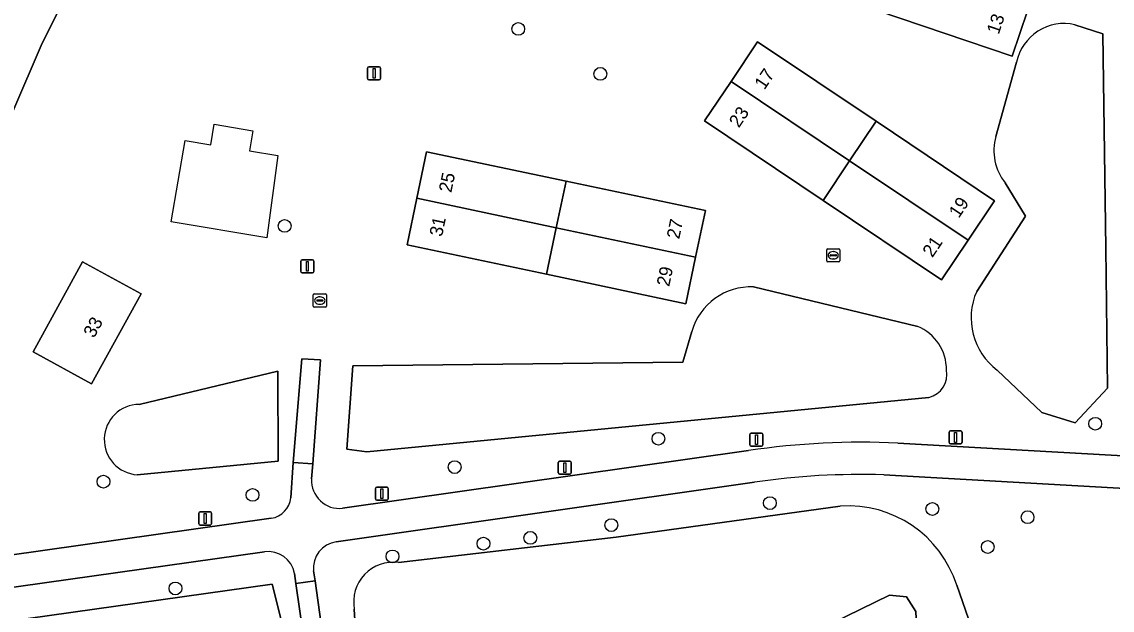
# Model space of a CAD drawing. Extents: x 159451 to 160664, y 388402 to 389723.
# Drawn here: x 159502.7 to 159586.1, y 389293.3 to 389338.3 of the extents above; entities that cross this region are included whole.
import ezdxf

# ---------------------------------------------------------------- set-up
doc = ezdxf.new("R2010")
doc.units = 0
for name, color, linetype in [('IMGEO_Boom', 7, 'Continuous'), ('IMGEO_Bouwland', 7, 'Continuous'), ('IMGEO_Groenvoorziening', 7, 'Continuous'), ('IMGEO_Lichtmast', 7, 'Continuous'), ('IMGEO_Loofbos', 7, 'Continuous'), ('IMGEO_Meer_plas_ven_vijver', 7, 'Continuous'), ('IMGEO_Pand', 7, 'Continuous'), ('IMGEO_Pand_nummerreeks', 7, 'Continuous'), ('IMGEO_Pand_vergunning_verleend', 7, 'Continuous'), ('IMGEO_Rijbaan_lokaal_gesloten', 7, 'Continuous'), ('IMGEO_Rioolput', 7, 'Continuous')]:
    doc.layers.add(name, color=color, linetype=linetype)

msp = doc.modelspace()

# ---------------------------------------------------------------- linework, layer by layer
at = {"layer": 'IMGEO_Boom'}
for centre in [(159540.673, 389337.725), (159546.954, 389334.287), (159522.8, 389322.657), (159584.813, 389307.527), (159551.396, 389306.381), (159535.811, 389304.209), (159508.939, 389303.101), (159520.344, 389302.083), (159559.924, 389301.457), (159572.353, 389301.007), (159579.641, 389300.381), (159547.792, 389299.774), (159538.012, 389298.356), (159541.597, 389298.799), (159531.052, 389297.376), (159576.591, 389298.104), (159514.448, 389294.93)]:
    msp.add_circle(centre, 0.489, dxfattribs=at)
at = {"layer": 'IMGEO_Bouwland'}
for points in [[(159521.25, 389297.74), (159493.172, 389293.777), (159486.712, 389292.863), (159536.847, 389188.304)], [(159525.256, 389283.811), (159524.796, 389287.372), (159523.669, 389295.299), (159523.555, 389296.061)]]:
    msp.add_lwpolyline(points, dxfattribs=at)
msp.add_lwpolyline([(159511.894, 389259.653), (159514.744, 389257.84), (159515.886, 389256.055), (159517.22, 389247.851), (159518.659, 389246.126), (159521.069, 389241.65), (159515.724, 389239.283), (159511.127, 389249.352), (159494.743, 389289.39), (159494.831, 389290.177), (159496.278, 389291.663), (159521.85, 389295.267), (159523.74, 389287.733), (159509.011, 389285.515), (159504.61, 389284.226)], close=True, dxfattribs=at)
msp.add_arc((159521.518, 389295.687), 2.071, 10.41627, 97.44331, dxfattribs=at)
at = {"layer": 'IMGEO_Groenvoorziening'}
for points in [[(159544.814, 389411.565), (159514.866, 389357.937), (159504.183, 389336.444), (159491.991, 389308.123), (159485.81, 389295.214), (159492.759, 389296.199), (159521.777, 389300.297)], [(159583.265, 389338.049), (159585.405, 389337.346)], [(159585.405, 389337.346), (159585.616, 389320.948), (159585.756, 389310.259), (159583.269, 389307.588), (159580.724, 389308.383), (159577.303, 389311.626)], [(159577.217, 389329.496), (159578.8, 389335.179)], [(159575.746, 389317.652), (159579.475, 389323.392), (159577.93, 389325.941)], [(159558.673, 389317.997), (159571.236, 389314.976)], [(159572.076, 389309.541), (159529.1, 389305.373), (159527.548, 389305.578), (159528.023, 389311.95), (159553.255, 389312.241), (159553.948, 389314.586)], [(159523.268, 389301.867), (159523.448, 389304.552), (159524.108, 389312.501), (159525.556, 389312.414), (159524.968, 389304.47), (159524.866, 389303.302)], [(159511.676, 389309.006), (159522.275, 389311.536), (159522.313, 389304.654)], [(159527.236, 389301.062), (159558.3, 389305.469)], [(159569.711, 389306.038), (159612.776, 389303.614), (159612.166, 389303.421), (159612.757, 389303.197), (159612.044, 389302.952), (159612.655, 389302.565), (159611.86, 389302.198), (159612.513, 389301.851), (159611.84, 389301.566), (159612.27, 389301.143), (159568.631, 389303.617)], [(159522.313, 389304.654), (159511.527, 389303.624)], [(159558.75, 389303.048), (159526.743, 389298.498)], [(159531.514, 389296.911), (159548.156, 389298.841), (159565.312, 389301.228)], [(159525.003, 389296.267), (159525.136, 389295.518), (159526.226, 389287.573), (159526.723, 389284.029)], [(159574.217, 389295.171), (159576.492, 389288.625), (159580.643, 389278.999), (159585.177, 389266.997), (159588.35, 389258.709)], [(159571.755, 389279.564), (159571.085, 389293.162), (159570.386, 389294.298), (159569.066, 389294.418), (159562.535, 389291.222)], [(159528.272, 389290.814), (159528.13, 389293.352)]]:
    msp.add_lwpolyline(points, dxfattribs=at)
for points in [[(159578.47, 389335.651), (159568.144, 389339.143), (159557.83, 389342.632), (159558.992, 389346.082), (159560.158, 389349.546), (159570.482, 389346.054), (159580.805, 389342.563), (159579.637, 389339.107)], [(159568.05, 389330.657), (159577.112, 389324.582), (159575.085, 389321.557), (159573.057, 389318.531), (159563.994, 389324.607), (159554.929, 389330.685), (159556.956, 389333.705), (159558.987, 389336.732)], [(159554.238, 389320.27), (159553.487, 389316.706), (159542.824, 389318.958), (159532.162, 389321.21), (159532.912, 389324.767), (159533.664, 389328.332), (159544.327, 389326.082), (159554.99, 389323.833)], [(159511.812, 389317.468), (159508.032, 389310.567), (159503.562, 389313.015), (159507.34, 389319.922)]]:
    msp.add_lwpolyline(points, close=True, dxfattribs=at)
for centre, radius, start, end in [((159582.45, 389334.409), 3.73, 77.37547, 168.0885), ((159580.971, 389328.4), 3.911, 163.72297, 218.95888), ((159558.496, 389313.264), 4.736, 87.85852, 163.79288), ((159580.344, 389315.626), 5.024, 156.21696, 232.75756), ((159569.834, 389311.66), 3.6, 359.71074, 67.08044), ((159571.661, 389311.298), 1.806, 283.27906, 10.96701), ((159511.697, 389306.312), 2.694, 90.44666, 266.3817), ((159566.832, 389249.071), 57.04, 87.10675, 98.60253), ((159566.807, 389249.211), 54.436, 88.07992, 98.51159), ((159526.998, 389303.184), 2.135, 176.82421, 276.40637), ((159521.497, 389302.056), 1.781, 279.04609, 353.91069), ((159565.905, 389292.525), 8.723, 17.65678, 93.89774), ((159527.037, 389296.475), 2.044, 98.26043, 185.83686), ((159531.116, 389293.901), 3.036, 82.46825, 190.41944)]:
    msp.add_arc(centre, radius, start, end, dxfattribs=at)
at = {"layer": 'IMGEO_Lichtmast'}
for p, q in [((159529.146, 389333.929), (159529.146, 389334.729)), ((159529.146, 389334.729), (159529.146, 389333.929)), ((159529.246, 389334.829), (159530.036, 389334.829)), ((159530.036, 389334.829), (159529.246, 389334.829)), ((159530.136, 389334.729), (159530.136, 389333.929)), ((159530.136, 389333.929), (159530.136, 389334.729)), ((159530.036, 389333.829), (159529.246, 389333.829)), ((159529.246, 389333.829), (159530.036, 389333.829)), ((159524.042, 389319.163), (159524.042, 389319.963)), ((159524.042, 389319.963), (159524.042, 389319.163)), ((159524.142, 389320.063), (159524.932, 389320.063)), ((159524.932, 389320.063), (159524.142, 389320.063)), ((159525.032, 389319.963), (159525.032, 389319.163)), ((159525.032, 389319.163), (159525.032, 389319.963)), ((159524.932, 389319.063), (159524.142, 389319.063)), ((159524.142, 389319.063), (159524.932, 389319.063)), ((159573.733, 389306.98), (159574.523, 389306.98)), ((159574.523, 389306.98), (159573.733, 389306.98)), ((159558.399, 389305.91), (159558.399, 389306.71)), ((159558.399, 389306.71), (159558.399, 389305.91)), ((159558.499, 389306.81), (159559.289, 389306.81)), ((159559.289, 389306.81), (159558.499, 389306.81)), ((159559.389, 389306.71), (159559.389, 389305.91)), ((159559.389, 389305.91), (159559.389, 389306.71)), ((159573.633, 389306.08), (159573.633, 389306.88)), ((159573.633, 389306.88), (159573.633, 389306.08)), ((159574.623, 389306.88), (159574.623, 389306.08)), ((159574.623, 389306.08), (159574.623, 389306.88)), ((159559.289, 389305.81), (159558.499, 389305.81)), ((159558.499, 389305.81), (159559.289, 389305.81)), ((159574.523, 389305.98), (159573.733, 389305.98)), ((159573.733, 389305.98), (159574.523, 389305.98)), ((159543.739, 389303.773), (159543.739, 389304.573)), ((159543.739, 389304.573), (159543.739, 389303.773)), ((159543.839, 389304.673), (159544.629, 389304.673)), ((159544.629, 389304.673), (159543.839, 389304.673)), ((159544.729, 389304.573), (159544.729, 389303.773)), ((159544.729, 389303.773), (159544.729, 389304.573)), ((159544.629, 389303.673), (159543.839, 389303.673)), ((159543.839, 389303.673), (159544.629, 389303.673)), ((159529.742, 389301.778), (159529.742, 389302.578)), ((159529.742, 389302.578), (159529.742, 389301.778)), ((159529.842, 389302.678), (159530.632, 389302.678)), ((159530.632, 389302.678), (159529.842, 389302.678)), ((159530.732, 389302.578), (159530.732, 389301.778)), ((159530.732, 389301.778), (159530.732, 389302.578)), ((159530.632, 389301.678), (159529.842, 389301.678)), ((159529.842, 389301.678), (159530.632, 389301.678)), ((159516.227, 389299.881), (159516.227, 389300.681)), ((159516.227, 389300.681), (159516.227, 389299.881)), ((159516.327, 389300.781), (159517.117, 389300.781)), ((159517.117, 389300.781), (159516.327, 389300.781)), ((159517.217, 389300.681), (159517.217, 389299.881)), ((159517.217, 389299.881), (159517.217, 389300.681)), ((159517.117, 389299.781), (159516.327, 389299.781)), ((159516.327, 389299.781), (159517.117, 389299.781))]:
    msp.add_line(p, q, dxfattribs=at)
for points in [[(159529.566, 389334.704), (159529.716, 389334.704), (159529.716, 389333.954), (159529.566, 389333.954), (159529.566, 389334.704)], [(159524.462, 389319.938), (159524.612, 389319.938), (159524.612, 389319.188), (159524.462, 389319.188), (159524.462, 389319.938)], [(159558.819, 389306.685), (159558.969, 389306.685), (159558.969, 389305.935), (159558.819, 389305.935), (159558.819, 389306.685)], [(159574.053, 389306.855), (159574.203, 389306.855), (159574.203, 389306.105), (159574.053, 389306.105), (159574.053, 389306.855)], [(159544.159, 389304.548), (159544.309, 389304.548), (159544.309, 389303.798), (159544.159, 389303.798), (159544.159, 389304.548)], [(159530.162, 389302.553), (159530.312, 389302.553), (159530.312, 389301.803), (159530.162, 389301.803), (159530.162, 389302.553)], [(159516.647, 389300.656), (159516.797, 389300.656), (159516.797, 389299.906), (159516.647, 389299.906), (159516.647, 389300.656)]]:
    msp.add_lwpolyline(points, dxfattribs=at)
for centre, start, end in [((159529.246, 389334.729), 90, 180), ((159529.246, 389334.729), 90, 180), ((159530.036, 389334.729), 0, 90), ((159530.036, 389334.729), 360, 90), ((159529.246, 389333.929), 180, 270), ((159529.246, 389333.929), 180, 270), ((159530.036, 389333.929), 270, 0), ((159530.036, 389333.929), 270, 0), ((159524.142, 389319.963), 90, 180), ((159524.142, 389319.963), 90, 180), ((159524.932, 389319.963), 0, 90), ((159524.932, 389319.963), 360, 90), ((159524.142, 389319.163), 180, 270), ((159524.142, 389319.163), 180, 270), ((159524.932, 389319.163), 270, 0), ((159524.932, 389319.163), 270, 0), ((159573.733, 389306.88), 90, 180), ((159573.733, 389306.88), 90, 180), ((159574.523, 389306.88), 0, 90), ((159574.523, 389306.88), 360, 90), ((159558.499, 389306.71), 90, 180), ((159558.499, 389306.71), 90, 180), ((159559.289, 389306.71), 0, 90), ((159559.289, 389306.71), 360, 90), ((159558.499, 389305.91), 180, 270), ((159558.499, 389305.91), 180, 270), ((159559.289, 389305.91), 270, 0), ((159559.289, 389305.91), 270, 0), ((159573.733, 389306.08), 180, 270), ((159573.733, 389306.08), 180, 270), ((159574.523, 389306.08), 270, 0), ((159574.523, 389306.08), 270, 0), ((159543.839, 389304.573), 90, 180), ((159543.839, 389304.573), 90, 180), ((159544.629, 389304.573), 0, 90), ((159544.629, 389304.573), 360, 90), ((159543.839, 389303.773), 180, 270), ((159543.839, 389303.773), 180, 270), ((159544.629, 389303.773), 270, 0), ((159544.629, 389303.773), 270, 0), ((159529.842, 389302.578), 90, 180), ((159529.842, 389302.578), 90, 180), ((159530.632, 389302.578), 0, 90), ((159530.632, 389302.578), 360, 90), ((159529.842, 389301.778), 180, 270), ((159529.842, 389301.778), 180, 270), ((159530.632, 389301.778), 270, 0), ((159530.632, 389301.778), 270, 0), ((159516.327, 389300.681), 90, 180), ((159516.327, 389300.681), 90, 180), ((159517.117, 389300.681), 0, 90), ((159517.117, 389300.681), 360, 90), ((159516.327, 389299.881), 180, 270), ((159516.327, 389299.881), 180, 270), ((159517.117, 389299.881), 270, 0), ((159517.117, 389299.881), 270, 0)]:
    msp.add_arc(centre, 0.1, start, end, dxfattribs=at)
at = {"layer": 'IMGEO_Loofbos'}
msp.add_lwpolyline([(159475.093, 389317.376), (159476.799, 389293.936), (159485.81, 389295.214), (159491.991, 389308.123), (159504.183, 389336.444), (159514.866, 389357.937), (159544.814, 389411.565)], dxfattribs=at)
at = {"layer": 'IMGEO_Meer_plas_ven_vijver'}
for points in [[(159585.405, 389337.346), (159583.265, 389338.049)], [(159577.303, 389311.626), (159580.724, 389308.383), (159583.269, 389307.588), (159585.756, 389310.259), (159585.616, 389320.948), (159585.405, 389337.346)], [(159578.8, 389335.179), (159577.217, 389329.496)], [(159577.93, 389325.941), (159579.475, 389323.392), (159575.746, 389317.652)], [(159571.236, 389314.976), (159558.673, 389317.997)], [(159553.948, 389314.586), (159553.255, 389312.241), (159528.023, 389311.95), (159527.548, 389305.578), (159529.1, 389305.373), (159572.076, 389309.541)], [(159522.313, 389304.654), (159522.275, 389311.536), (159511.676, 389309.006)], [(159511.527, 389303.624), (159522.313, 389304.654)], [(159565.312, 389301.228), (159548.156, 389298.841), (159531.514, 389296.911)], [(159581.411, 389257.784), (159588.35, 389258.709), (159585.177, 389266.997), (159580.643, 389278.999), (159576.492, 389288.625), (159574.217, 389295.171)], [(159562.535, 389291.222), (159569.066, 389294.418), (159570.386, 389294.298), (159571.085, 389293.162), (159571.755, 389279.564)], [(159528.13, 389293.352), (159528.272, 389290.814)]]:
    msp.add_lwpolyline(points, dxfattribs=at)
msp.add_lwpolyline([(159521.069, 389241.65), (159518.659, 389246.126), (159517.22, 389247.851), (159515.886, 389256.055), (159514.744, 389257.84), (159511.894, 389259.653), (159504.61, 389284.226), (159509.011, 389285.515), (159523.74, 389287.733), (159521.85, 389295.267), (159496.278, 389291.663), (159494.831, 389290.177), (159494.743, 389289.39), (159511.127, 389249.352), (159515.724, 389239.283)], close=True, dxfattribs=at)
for centre, radius, start, end in [((159582.45, 389334.409), 3.73, 77.37547, 168.0885), ((159580.971, 389328.4), 3.911, 163.72297, 218.95888), ((159558.496, 389313.264), 4.736, 87.85852, 163.79288), ((159580.344, 389315.626), 5.024, 156.21696, 232.75756), ((159569.834, 389311.66), 3.6, 359.71074, 67.08044), ((159571.661, 389311.298), 1.806, 283.27906, 10.96701), ((159511.697, 389306.312), 2.694, 90.44666, 266.3817), ((159565.905, 389292.525), 8.723, 17.65678, 93.89774), ((159531.116, 389293.901), 3.036, 82.46825, 190.41944)]:
    msp.add_arc(centre, radius, start, end, dxfattribs=at)
at = {"layer": 'IMGEO_Pand'}
for points in [[(159569.312, 389342.595), (159568.144, 389339.143), (159578.47, 389335.651), (159579.637, 389339.107)], [(159558.987, 389336.732), (159556.956, 389333.705), (159566.021, 389327.63), (159568.05, 389330.657)], [(159556.956, 389333.705), (159554.929, 389330.685), (159563.994, 389324.607), (159566.021, 389327.63)], [(159568.05, 389330.657), (159566.021, 389327.63), (159575.085, 389321.557), (159577.112, 389324.582)], [(159544.327, 389326.082), (159533.664, 389328.332), (159532.912, 389324.767), (159543.575, 389322.518)], [(159566.021, 389327.63), (159563.994, 389324.607), (159573.057, 389318.531), (159575.085, 389321.557)], [(159554.99, 389323.833), (159544.327, 389326.082), (159543.575, 389322.518), (159554.238, 389320.27)], [(159543.575, 389322.518), (159532.912, 389324.767), (159532.162, 389321.21), (159542.824, 389318.958)], [(159554.238, 389320.27), (159543.575, 389322.518), (159542.824, 389318.958), (159553.487, 389316.706)], [(159511.812, 389317.468), (159507.34, 389319.922), (159503.562, 389313.015), (159508.032, 389310.567)]]:
    msp.add_lwpolyline(points, close=True, dxfattribs=at)
at = {"layer": 'IMGEO_Pand_vergunning_verleend'}
msp.add_lwpolyline([(159514.125, 389322.975), (159515.179, 389329.187), (159517.143, 389328.854), (159517.413, 389330.443), (159520.37, 389329.941), (159520.111, 389328.409), (159522.274, 389328.042), (159521.436, 389321.734)], close=True, dxfattribs=at)
at = {"layer": 'IMGEO_Rijbaan_lokaal_gesloten'}
for points in [[(159523.448, 389304.552), (159524.968, 389304.47), (159525.556, 389312.414), (159524.108, 389312.501)], [(159525.136, 389295.518), (159523.669, 389295.299), (159524.796, 389287.372), (159526.226, 389287.573)]]:
    msp.add_lwpolyline(points, close=True, dxfattribs=at)
for points in [[(159558.3, 389305.469), (159527.236, 389301.062)], [(159612.776, 389303.614), (159569.711, 389306.038)], [(159524.866, 389303.302), (159524.968, 389304.47), (159523.448, 389304.552), (159523.268, 389301.867)], [(159568.631, 389303.617), (159612.27, 389301.143), (159611.84, 389301.566), (159612.513, 389301.851), (159611.86, 389302.198), (159612.655, 389302.565), (159612.044, 389302.952), (159612.757, 389303.197), (159612.166, 389303.421), (159612.776, 389303.614)], [(159526.743, 389298.498), (159558.75, 389303.048)], [(159521.777, 389300.297), (159492.759, 389296.199), (159485.81, 389295.214), (159476.799, 389293.936), (159476.493, 389293.892), (159475.498, 389293.751), (159474.699, 389293.638), (159473.535, 389293.473)], [(159473.627, 389291.013), (159474.893, 389291.192), (159475.691, 389291.305), (159476.671, 389291.444), (159476.978, 389291.487), (159483.087, 389292.351), (159486.712, 389292.863), (159493.172, 389293.777), (159521.25, 389297.74)], [(159523.555, 389296.061), (159523.669, 389295.299), (159525.136, 389295.518), (159525.003, 389296.267)]]:
    msp.add_lwpolyline(points, dxfattribs=at)
for centre, radius, start, end in [((159566.832, 389249.071), 57.04, 87.10675, 98.60253), ((159566.807, 389249.211), 54.436, 88.07992, 98.51159), ((159526.998, 389303.184), 2.135, 176.82421, 276.40637), ((159521.497, 389302.056), 1.781, 279.04609, 353.91069), ((159527.037, 389296.475), 2.044, 98.26043, 185.83686), ((159521.518, 389295.687), 2.071, 10.41627, 97.44331)]:
    msp.add_arc(centre, radius, start, end, dxfattribs=at)
at = {"layer": 'IMGEO_Rioolput'}
for p, q in [((159564.271, 389319.987), (159564.271, 389320.839)), ((159564.346, 389320.913), (159565.198, 389320.913)), ((159564.53, 389320.407), (159564.53, 389320.419)), ((159564.968, 389320.37), (159564.57, 389320.37)), ((159564.573, 389320.456), (159564.971, 389320.456)), ((159564.759, 389320.693), (159564.784, 389320.693)), ((159565.014, 389320.419), (159565.014, 389320.407)), ((159565.272, 389320.839), (159565.272, 389319.987)), ((159565.198, 389319.913), (159564.346, 389319.913)), ((159564.782, 389320.133), (159564.757, 389320.133)), ((159524.994, 389316.525), (159524.994, 389317.377)), ((159525.069, 389317.451), (159525.921, 389317.451)), ((159525.296, 389316.994), (159525.694, 389316.994)), ((159525.482, 389317.231), (159525.507, 389317.231)), ((159525.995, 389317.377), (159525.995, 389316.525)), ((159525.921, 389316.451), (159525.069, 389316.451)), ((159525.253, 389316.945), (159525.253, 389316.957)), ((159525.691, 389316.908), (159525.293, 389316.908)), ((159525.505, 389316.671), (159525.48, 389316.671)), ((159525.737, 389316.957), (159525.737, 389316.945))]:
    msp.add_line(p, q, dxfattribs=at)
for points in [[(159564.271, 389319.987), (159564.271, 389320.839)], [(159564.346, 389320.913), (159565.198, 389320.913)], [(159565.272, 389320.839), (159565.272, 389319.987)], [(159565.198, 389319.913), (159564.346, 389319.913)], [(159524.994, 389316.525), (159524.994, 389317.377)], [(159525.069, 389317.451), (159525.921, 389317.451)], [(159525.995, 389317.377), (159525.995, 389316.525)], [(159525.921, 389316.451), (159525.069, 389316.451)]]:
    msp.add_lwpolyline(points, dxfattribs=at)
for centre, radius, start, end in [((159564.348, 389320.837), 0.0765, 91.55205, 178.44795), ((159564.348, 389320.837), 0.0765, 91.55205, 178.44795), ((159564.57, 389320.416), 0.0403, 85.87752, 175.75265), ((159564.567, 389320.406), 0.0366, 178.93798, 274.71019), ((159564.971, 389320.413), 0.043, 264.86636, 352.45326), ((159564.975, 389320.418), 0.0386, 1.73085, 96.63898), ((159565.196, 389320.837), 0.0765, 1.55205, 88.44795), ((159565.196, 389320.837), 0.0765, 1.55205, 88.44795), ((159564.348, 389319.989), 0.0765, 181.55205, 268.44795), ((159564.348, 389319.989), 0.0765, 181.55205, 268.44795), ((159565.196, 389319.989), 0.0765, 271.55205, 358.44795), ((159565.196, 389319.989), 0.0765, 271.55205, 358.44795), ((159525.071, 389317.375), 0.0765, 91.55205, 178.44795), ((159525.071, 389317.375), 0.0765, 91.55205, 178.44795), ((159525.293, 389316.954), 0.0403, 85.87752, 175.75265), ((159525.698, 389316.956), 0.0386, 1.73085, 96.63898), ((159525.919, 389317.375), 0.0765, 1.55205, 88.44795), ((159525.919, 389317.375), 0.0765, 1.55205, 88.44795), ((159525.071, 389316.527), 0.0765, 181.55205, 268.44795), ((159525.071, 389316.527), 0.0765, 181.55205, 268.44795), ((159525.29, 389316.944), 0.0366, 178.93798, 274.71019), ((159525.694, 389316.951), 0.043, 264.86636, 352.45326), ((159525.919, 389316.527), 0.0765, 271.55205, 358.44795), ((159525.919, 389316.527), 0.0765, 271.55205, 358.44795)]:
    msp.add_arc(centre, radius, start, end, dxfattribs=at)
for centre, major_axis, ratio, start_param, end_param in [((159564.758, 389320.413), (-0.387, 0.002), 0.722429, 4.712389, 7.853982), ((159564.783, 389320.413), (-0.39, 0.002), 0.717154, 1.570796, 4.712389), ((159525.481, 389316.951), (-0.387, 0.002), 0.722429, 4.712389, 7.853982), ((159525.506, 389316.951), (-0.39, 0.002), 0.717154, 1.570796, 4.712389)]:
    msp.add_ellipse(centre, major_axis=major_axis, ratio=ratio, start_param=start_param, end_param=end_param, dxfattribs=at)

# ---------------------------------------------------------------- texts
at = {"layer": 'IMGEO_Pand_nummerreeks'}
for s, rotation, p in [('13', 71.33325, (159577.429, 389337.254)), ('17', 56.13268, (159559.502, 389333.012)), ('23', 56.13268, (159557.552, 389330.107)), ('25', 78.08842, (159535.55, 389325.159)), ('19', 56.17278, (159574.375, 389323.193)), ('31', 78.08842, (159534.839, 389321.791)), ('27', 78.09415, (159552.987, 389321.604)), ('21', 56.17278, (159572.358, 389320.182)), ('29', 78.09415, (159552.221, 389317.972)), ('33', 61.2893, (159508.218, 389314.03))]:
    msp.add_text(s, height=1, rotation=rotation, dxfattribs=at).set_placement(p)

doc.saveas('drawing.dxf')
